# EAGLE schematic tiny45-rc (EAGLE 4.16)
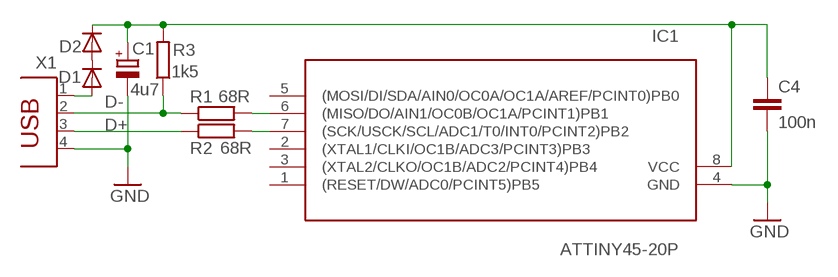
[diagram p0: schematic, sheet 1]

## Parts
C1  4u7  CPOL-EUE2-5  [E2-5]
C4  100n  C-EU025-024X044  [C025-024X044]
D1  1N4148  [DO35-10]
D2  1N4148  [DO35-10]
IC1  ATTINY45-20P  [DIL08]
R1  68R  R-EU_0207/10  [0207/10]
R2  68R  R-EU_0207/10  [0207/10]
R3  1k5  R-EU_0207/10  [0207/10]
X1  PN61729  [PN61729]

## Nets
D+: R2.1 X1.3
D-: R1.1 R3.1 X1.2
GND: C1.- C4.2 IC1.4(GND) X1.4
N$1: IC1.6((MISO/DO/AIN1/OC0B/OC1A/PCINT1)PB1) R1.2
N$2: IC1.7((SCK/USCK/SCL/ADC1/T0/INT0/PCINT2)PB2) R2.2
N$5: D1.A X1.1
N$6: D1.C D2.A
VCC: C1.+ C4.1 D2.C IC1.8(VCC) R3.2
Unconnected: IC1.1((RESET/DW/ADC0/PCINT5)PB5) IC1.2((XTAL1/CLKI/OC1B/ADC3/PCINT3)PB3) IC1.3((XTAL2/CLKO/OC1B/ADC2/PCINT4)PB4) IC1.5((MOSI/DI/SDA/AIN0/OC0A/OC1A/AREF/PCINT0)PB0)

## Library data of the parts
C1 = rcl:CPOL-EU: POLARIZED CAPACITOR, European symbol
C4 = rcl:C-EU: CAPACITOR, European symbol
D1 D2 = diode:1N4148: DIODE
IC1 = avr:ATTINY45: MICROCONTROLLER 4 Kbytes FLASH 256 bytes EEPROM 256 bytes RAM 4-channel 10 bit ADC USI
R1-R3 = rcl:R-EU_: RESISTOR, European symbol
X1 = con-berg:PN61729: BERG USB connector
